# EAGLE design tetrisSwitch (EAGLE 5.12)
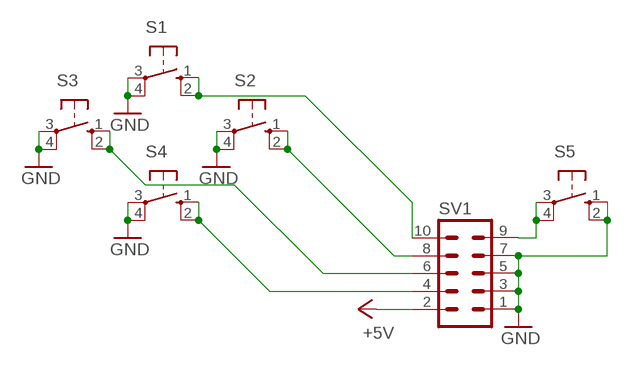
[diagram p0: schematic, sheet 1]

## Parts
S1  10-XX  [B3F-10XX]
S2  10-XX  [B3F-10XX]
S3  10-XX  [B3F-10XX]
S4  10-XX  [B3F-10XX]
S5  10-XX  [B3F-10XX]
SV1  ML10  [ML10]

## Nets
+5V: SV1.2
GND: S1.3(P) S1.4(P1) S2.3(P) S2.4(P1) S3.3(P) S3.4(P1) S4.3(P) S4.4(P1) S5.1(S) S5.2(S1) SV1.1 SV1.3 SV1.5 SV1.7
N$1: S5.3(P) S5.4(P1) SV1.9
N$2: S2.1(S) S2.2(S1) SV1.8
N$3: S3.1(S) S3.2(S1) SV1.6
N$4: S4.1(S) S4.2(S1) SV1.4
N$5: S1.1(S) S1.2(S1) SV1.10

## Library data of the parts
S1-S5 = switch-omron:10-XX: OMRON SWITCH; MPN: B3F-1000; OC_FARNELL: 176432; OC_NEWARK: 36M3542
SV1 = con-harting-ml:ML10: HARTING; OC_FARNELL: unknown; OC_NEWARK: unknown

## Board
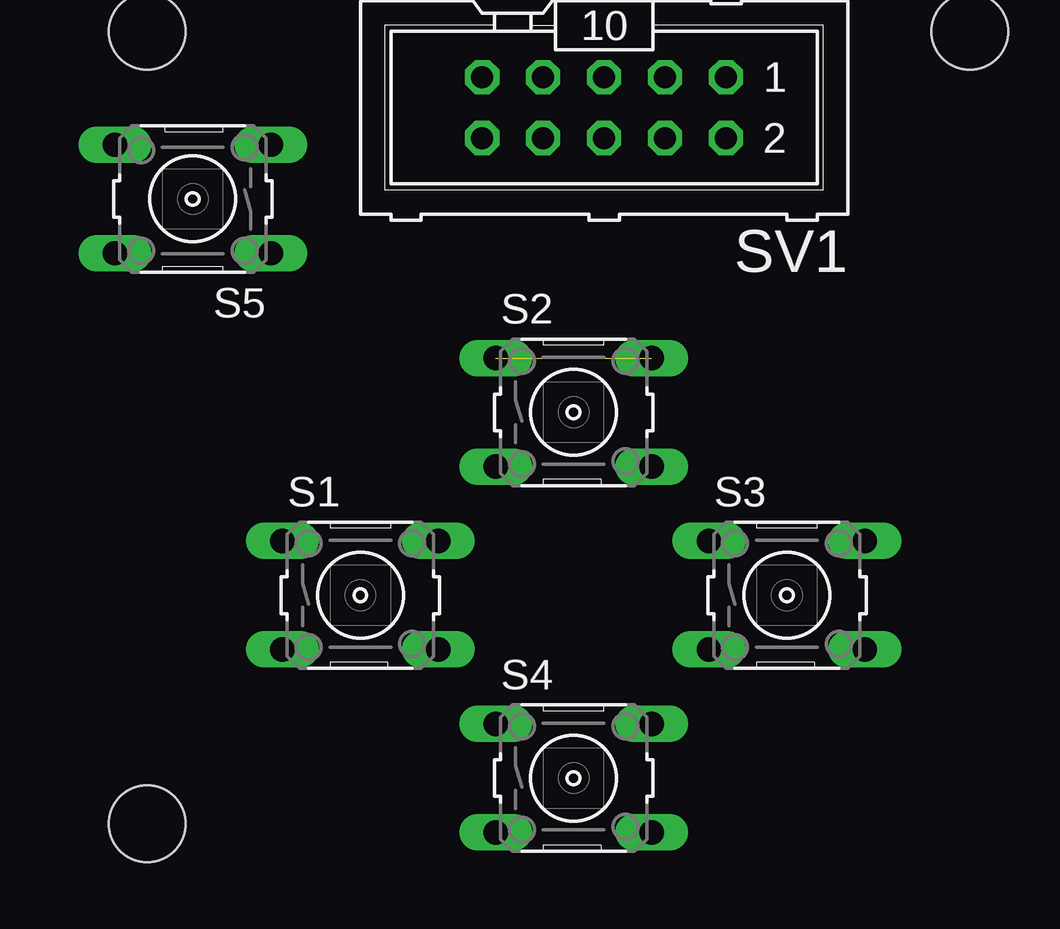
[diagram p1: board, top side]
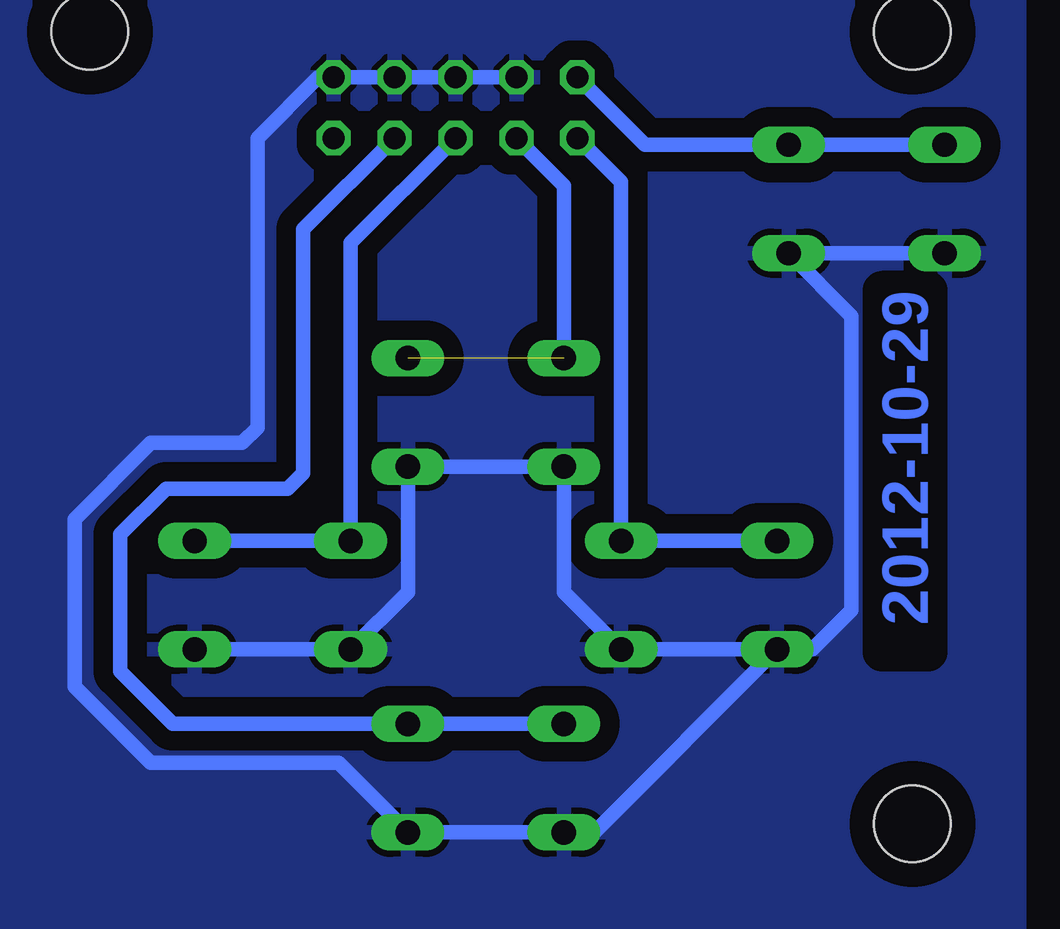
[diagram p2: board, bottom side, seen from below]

No outline drawn. Coordinates in mm, seen from the top.
Copper layers (1*16): Top 0.035mm / dielectric 1.5mm / Bottom 0.035mm
Design rules "default": minimum track width 10mil, minimum drill 24mil, track to track 8mil, track to pad 8mil, pad to pad 8mil, via to via 8mil, smd to smd 8mil, copper to edge 40mil, drill to drill 8mil, minimum pad ring 10mil, minimum via ring 8mil, stop-mask expansion 4mil, vias tented up to drill 0mil, thermal gap 10mil
Holes 3.2 mm at 22.86,26.04 22.86,59.05 57.15,59.05

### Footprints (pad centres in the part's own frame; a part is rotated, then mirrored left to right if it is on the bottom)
B3F-10XX = drill 1.016 long: 1 -3.251,2.261; 2 3.251,2.261; 3 -3.251,-2.261; 4 3.251,-2.261
ML10 = drill 0.914 octagon: 1 -5.08,-1.27; 2 -5.08,1.27; 3 -2.54,-1.27; 4 -2.54,1.27; 5 0,-1.27; 6 0,1.27; 7 2.54,-1.27; 8 2.54,1.27; 9 5.08,-1.27; 10 5.08,1.27

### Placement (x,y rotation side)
S1  31.75,35.56 0 top
S2  40.64,43.18 0 top
S3  49.53,35.56 0 top
S4  40.64,27.94 0 top
S5  24.77,52.07 180 top
SV1  41.91,55.88 180 top

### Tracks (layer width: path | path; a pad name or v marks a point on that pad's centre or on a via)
GND
  Bottom 0.61: S3.4 S3.3 43.89,35.69 S2.4 S2.3 37.39,35.69 S1.4 S1.3 | S1.3 36.12,25.68 S4.3 S4.4 46.79,28.57 54.61,28.57 57.78,31.75 57.78,38.73 54.61,41.91 50.8,41.91 50.16,42.55 50.16,54.61 47.62,57.15 SV1.1 SV1.3 SV1.5 SV1.7 | S1.3 27.03,33.3 25.4,34.92 25.4,47.19 S5.1 S5.2
  pour Bottom (isolate 0.813): 18.41,63.5 61.59,63.5 61.59,21.59 18.41,21.59
N$1
  Bottom 0.61: S5.4 S5.3 34.01,54.33 SV1.9
N$2  (1 unrouted)
  Bottom 0.61: S2.1 37.39,52.63 SV1.8
N$3
  Bottom 0.61: SV1.6 46.28,50.24 S3.1 S3.2
N$4
  Bottom 0.61: SV1.4 48.26,50.8 48.26,40.64 48.9,40.01 53.98,40.01 55.88,38.1 55.88,32.38 53.7,30.2 S4.2 S4.1
N$5
  Bottom 0.61: SV1.10 35,52.78 S1.2 S1.1

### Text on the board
Bottom: 2012-10-29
